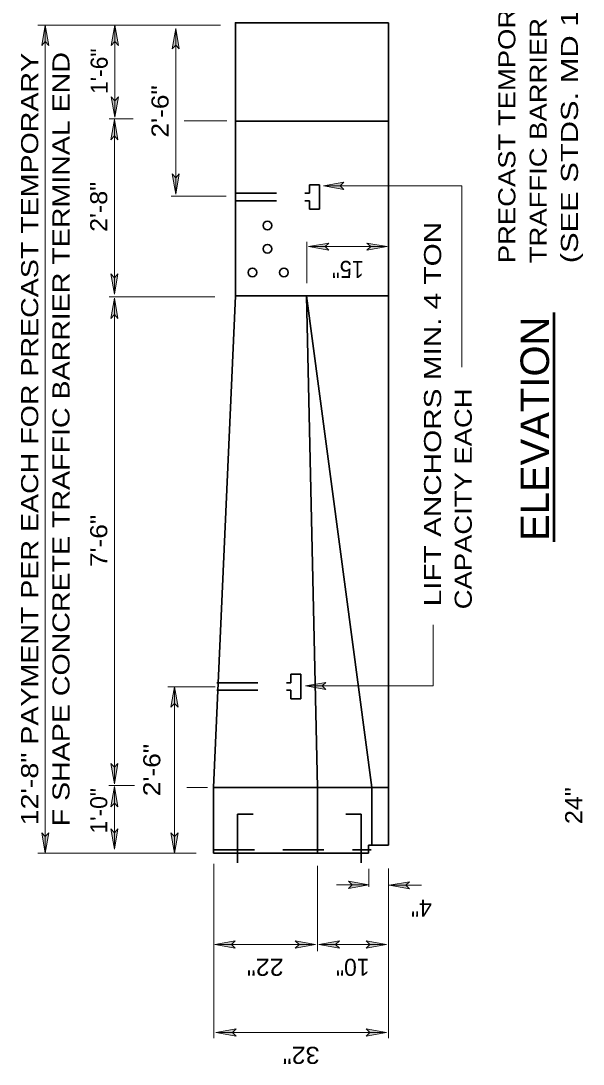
# Model space of a CAD drawing. Extents: x 12.6 to 19.4, y 6.1 to 16.3.
# Drawn here: x 15.209 to 17.184, y 8.18 to 11.844 of the extents above; entities that cross this region are included whole.
import ezdxf
from ezdxf.enums import TextEntityAlignment as Align

# ---------------------------------------------------------------- set-up
doc = ezdxf.new("R2010")
doc.units = 0
doc.header["$LTSCALE"] = 0.024
doc.linetypes.add('LONG_DASHED', pattern=[7.5, 6, -1.5])
for name, color, linetype, lineweight in [('1', 7, 'Continuous', 35), ('10', 7, 'Continuous', 13), ('12', 7, 'Continuous', 53)]:
    doc.layers.add(name, color=color, linetype=linetype, lineweight=lineweight)

msp = doc.modelspace()

# ---------------------------------------------------------------- hatches: boundary and pattern name
at = {"layer": '10'}
for points in [[(15.2821, 11.7573), (15.2947, 11.8288), (15.3073, 11.7573), (15.2947, 11.7708)], [(15.5263, 11.7574), (15.5389, 11.8289), (15.5515, 11.7574), (15.5389, 11.7709)], [(15.7401, 11.7452), (15.7527, 11.8167), (15.7653, 11.7452), (15.7527, 11.7587)], [(15.5515, 11.5766), (15.5389, 11.5051), (15.5263, 11.5766), (15.5389, 11.5631)], [(15.5247, 11.4261), (15.5373, 11.4976), (15.5499, 11.4261), (15.5373, 11.4396)], [(15.7653, 11.3065), (15.7527, 11.235), (15.7401, 11.3065), (15.7527, 11.293)], [(16.3439, 11.2517), (16.2724, 11.2643), (16.3439, 11.2769), (16.3304, 11.2643)], [(16.2912, 11.0383), (16.2197, 11.0509), (16.2912, 11.0635), (16.2777, 11.0509)], [(16.4247, 11.0635), (16.4962, 11.0509), (16.4247, 11.0383), (16.4382, 11.0509)], [(15.5499, 10.955), (15.5373, 10.8835), (15.5247, 10.955), (15.5373, 10.9415)], [(15.5248, 10.7985), (15.5374, 10.87), (15.55, 10.7985), (15.5374, 10.812)], [(15.7362, 9.4331), (15.7488, 9.5046), (15.7614, 9.4331), (15.7488, 9.4466)], [(16.2806, 9.4951), (16.2091, 9.5077), (16.2806, 9.5203), (16.2671, 9.5077)], [(15.55, 9.2359), (15.5374, 9.1644), (15.5248, 9.2359), (15.5374, 9.2224)], [(15.5248, 9.0831), (15.5374, 9.1546), (15.55, 9.0831), (15.5374, 9.0966)], [(15.3073, 8.9921), (15.2947, 8.9206), (15.2821, 8.9921), (15.2947, 8.9786)], [(15.55, 9.0056), (15.5374, 8.9341), (15.5248, 9.0056), (15.5374, 8.9921)], [(15.7614, 8.9921), (15.7488, 8.9206), (15.7362, 8.9921), (15.7488, 8.9786)], [(16.3596, 8.8218), (16.4311, 8.8092), (16.3596, 8.7966), (16.3731, 8.8092)], [(16.5743, 8.7952), (16.5028, 8.8078), (16.5743, 8.8204), (16.5608, 8.8078)], [(15.9619, 8.5873), (15.8904, 8.5999), (15.9619, 8.6125), (15.9484, 8.5999)], [(16.1728, 8.6125), (16.2443, 8.5999), (16.1728, 8.5873), (16.1863, 8.5999)], [(16.3277, 8.5873), (16.2562, 8.5999), (16.3277, 8.6125), (16.3142, 8.5999)], [(16.4219, 8.6125), (16.4934, 8.5999), (16.4219, 8.5873), (16.4354, 8.5999)], [(15.9653, 8.278), (15.8938, 8.2906), (15.9653, 8.3032), (15.9518, 8.2906)], [(16.4219, 8.3032), (16.4934, 8.2906), (16.4219, 8.278), (16.4354, 8.2906)]]:
    msp.add_hatch(color=256, dxfattribs=at).paths.add_polyline_path(points)

# ---------------------------------------------------------------- linework, layer by layer
at = {"layer": '1'}
for p, q in [((16.5, 8.9484), (16.5, 11.8374)), ((16.5, 10.8779), (15.9627, 10.8779)), ((16.4424, 9.1509), (16.2122, 10.8779)), ((16.2505, 9.1509), (16.2122, 10.8779)), ((15.8859, 9.1509), (16.5, 9.1509)), ((16.2505, 8.9206), (16.2505, 9.1509)), ((16.4424, 8.9484), (16.4424, 9.1509)), ((16.4298, 8.9206), (16.4298, 8.9484)), ((16.5, 8.9484), (16.4298, 8.9484)), ((16.4298, 8.9206), (15.8859, 8.9206)), ((15.9699, 8.9211), (15.9699, 8.887)), ((16.4049, 8.9211), (16.4049, 8.887))]:
    msp.add_line(p, q, dxfattribs=at)
at = {"layer": '1', "linetype": 'LONG_DASHED'}
for p, q in [((16.2226, 11.2681), (16.2577, 11.2681)), ((16.2577, 11.1822), (16.2577, 11.2681)), ((15.9625, 11.212), (16.2226, 11.212)), ((16.2226, 11.1822), (16.2226, 11.212)), ((16.2226, 11.1822), (16.2577, 11.1822)), ((16.1578, 9.5491), (16.1928, 9.5491)), ((16.1928, 9.4632), (16.1928, 9.5491)), ((15.8977, 9.493), (16.1578, 9.493)), ((16.1578, 9.4632), (16.1578, 9.493)), ((16.1578, 9.4632), (16.1928, 9.4632)), ((16.3501, 9.0577), (16.4049, 9.0577)), ((16.4049, 8.9211), (16.4049, 9.0577)), ((15.8856, 8.9326), (16.4395, 8.9326))]:
    msp.add_line(p, q, dxfattribs=at)
at = {"layer": '1'}
for points in [[(16.5, 11.8374), (15.9627, 11.8374), (15.9627, 11.4919), (16.5, 11.4919)], [(15.8859, 8.9206), (15.8859, 9.1509), (15.9627, 10.8779), (15.9627, 11.4919)]]:
    msp.add_lwpolyline(points, dxfattribs=at)
at = {"layer": '1', "linetype": 'LONG_DASHED'}
for points in [[(15.9625, 11.2383), (16.2226, 11.2383), (16.2226, 11.2681)], [(15.8977, 9.5193), (16.1578, 9.5193), (16.1578, 9.5491)], [(15.9699, 8.9211), (15.9699, 9.0577), (16.0247, 9.0577)]]:
    msp.add_lwpolyline(points, dxfattribs=at)
at = {"layer": '1'}
for centre in [(16.0749, 11.1247), (16.0749, 11.0434), (16.0222, 10.9603), (16.1332, 10.9603)]:
    msp.add_circle(centre, 0.0152, dxfattribs=at)
at = {"layer": '10'}
for p, q in [((15.91, 11.8288), (15.2683, 11.8288)), ((15.2947, 11.8288), (15.2821, 11.7573)), ((15.2947, 8.9206), (15.2947, 11.8288)), ((15.2947, 11.8288), (15.3073, 11.7573)), ((15.5389, 11.8289), (15.5263, 11.7574)), ((15.5389, 11.5051), (15.5389, 11.8289)), ((15.5389, 11.8289), (15.5515, 11.7574)), ((15.7527, 11.8167), (15.7401, 11.7452)), ((15.7527, 11.235), (15.7527, 11.8167)), ((15.7527, 11.8167), (15.7653, 11.7452)), ((15.5389, 11.5051), (15.5263, 11.5766)), ((15.5389, 11.5051), (15.5515, 11.5766)), ((15.5195, 11.5001), (15.6033, 11.5001)), ((15.5373, 11.4976), (15.5247, 11.4261)), ((15.5373, 10.8835), (15.5373, 11.4976)), ((15.5373, 11.4976), (15.5499, 11.4261)), ((15.933, 11.4932), (15.7822, 11.4932)), ((15.7527, 11.235), (15.7401, 11.3065)), ((15.7527, 11.235), (15.7653, 11.3065)), ((16.2724, 11.2643), (16.3439, 11.2769)), ((16.758, 11.2643), (16.2724, 11.2643)), ((16.2724, 11.2643), (16.3439, 11.2517)), ((16.758, 11.2643), (16.758, 10.6272)), ((15.9297, 11.2285), (15.7373, 11.2285)), ((16.2132, 10.9226), (16.2132, 11.068)), ((16.2197, 11.0509), (16.2912, 11.0635)), ((16.2197, 11.0509), (16.4962, 11.0509)), ((16.2197, 11.0509), (16.2912, 11.0383)), ((16.4962, 11.0509), (16.4247, 11.0635)), ((16.4962, 11.0509), (16.4247, 11.0383)), ((15.5373, 10.8835), (15.5247, 10.955)), ((15.5373, 10.8835), (15.5499, 10.955)), ((15.8904, 10.8747), (15.5195, 10.8747)), ((15.5374, 10.87), (15.5248, 10.7985)), ((15.5374, 9.1644), (15.5374, 10.87)), ((15.5374, 10.87), (15.55, 10.7985)), ((16.6576, 9.7223), (16.6576, 9.5077)), ((15.8914, 9.5046), (15.7246, 9.5046)), ((15.7488, 9.5046), (15.7362, 9.4331)), ((15.7488, 8.9206), (15.7488, 9.5046)), ((15.7488, 9.5046), (15.7614, 9.4331)), ((16.2091, 9.5077), (16.2806, 9.5203)), ((16.6576, 9.5077), (16.2091, 9.5077)), ((16.2091, 9.5077), (16.2806, 9.4951)), ((15.5374, 9.1644), (15.5248, 9.2359)), ((15.5374, 9.1644), (15.55, 9.2359)), ((15.5177, 9.1579), (15.6076, 9.1579)), ((15.5374, 9.1546), (15.5248, 9.0831)), ((15.5374, 9.1546), (15.5374, 8.9341)), ((15.5374, 9.1546), (15.55, 9.0831)), ((15.8641, 9.1509), (15.792, 9.1509)), ((15.2947, 8.9206), (15.2821, 8.9921)), ((15.2947, 8.9206), (15.3073, 8.9921)), ((15.5374, 8.9341), (15.5248, 9.0056)), ((15.5374, 8.9341), (15.55, 9.0056)), ((15.7488, 8.9206), (15.7362, 8.9921)), ((15.7488, 8.9206), (15.7614, 8.9921)), ((15.8248, 8.9206), (15.2683, 8.9206)), ((15.887, 8.8828), (15.887, 8.2709)), ((16.2508, 8.8762), (16.2508, 8.5767)), ((16.4312, 8.8653), (16.4312, 8.8026)), ((16.5, 8.8664), (16.5, 8.2709)), ((16.3178, 8.8092), (16.4311, 8.8092)), ((16.4311, 8.8092), (16.3596, 8.8218)), ((16.4311, 8.8092), (16.3596, 8.7966)), ((16.5028, 8.8078), (16.5743, 8.8204)), ((16.5028, 8.8078), (16.6161, 8.8078)), ((16.5028, 8.8078), (16.5743, 8.7952)), ((15.8904, 8.5999), (15.9619, 8.6125)), ((16.2443, 8.5999), (16.1728, 8.6125)), ((16.2562, 8.5999), (16.3277, 8.6125)), ((16.4934, 8.5999), (16.4219, 8.6125)), ((16.2443, 8.5999), (15.8904, 8.5999)), ((15.8904, 8.5999), (15.9619, 8.5873)), ((16.2443, 8.5999), (16.1728, 8.5873)), ((16.4934, 8.5999), (16.2562, 8.5999)), ((16.2562, 8.5999), (16.3277, 8.5873)), ((16.4934, 8.5999), (16.4219, 8.5873)), ((15.8938, 8.2906), (15.9653, 8.3032)), ((16.4934, 8.2906), (15.8938, 8.2906)), ((15.8938, 8.2906), (15.9653, 8.278)), ((16.4934, 8.2906), (16.4219, 8.3032)), ((16.4934, 8.2906), (16.4219, 8.278))]:
    msp.add_line(p, q, dxfattribs=at)
for points in [[(15.2821, 11.7573), (15.2947, 11.8288), (15.3073, 11.7573), (15.2947, 11.7708)], [(15.5263, 11.7574), (15.5389, 11.8289), (15.5515, 11.7574), (15.5389, 11.7709)], [(15.7401, 11.7452), (15.7527, 11.8167), (15.7653, 11.7452), (15.7527, 11.7587)], [(15.5515, 11.5766), (15.5389, 11.5051), (15.5263, 11.5766), (15.5389, 11.5631)], [(15.5247, 11.4261), (15.5373, 11.4976), (15.5499, 11.4261), (15.5373, 11.4396)], [(15.7653, 11.3065), (15.7527, 11.235), (15.7401, 11.3065), (15.7527, 11.293)], [(16.3439, 11.2517), (16.2724, 11.2643), (16.3439, 11.2769), (16.3304, 11.2643)], [(16.2912, 11.0383), (16.2197, 11.0509), (16.2912, 11.0635), (16.2777, 11.0509)], [(16.4247, 11.0635), (16.4962, 11.0509), (16.4247, 11.0383), (16.4382, 11.0509)], [(15.5499, 10.955), (15.5373, 10.8835), (15.5247, 10.955), (15.5373, 10.9415)], [(15.5248, 10.7985), (15.5374, 10.87), (15.55, 10.7985), (15.5374, 10.812)], [(15.7362, 9.4331), (15.7488, 9.5046), (15.7614, 9.4331), (15.7488, 9.4466)], [(16.2806, 9.4951), (16.2091, 9.5077), (16.2806, 9.5203), (16.2671, 9.5077)], [(15.55, 9.2359), (15.5374, 9.1644), (15.5248, 9.2359), (15.5374, 9.2224)], [(15.5248, 9.0831), (15.5374, 9.1546), (15.55, 9.0831), (15.5374, 9.0966)], [(15.3073, 8.9921), (15.2947, 8.9206), (15.2821, 8.9921), (15.2947, 8.9786)], [(15.55, 9.0056), (15.5374, 8.9341), (15.5248, 9.0056), (15.5374, 8.9921)], [(15.7614, 8.9921), (15.7488, 8.9206), (15.7362, 8.9921), (15.7488, 8.9786)], [(16.3596, 8.8218), (16.4311, 8.8092), (16.3596, 8.7966), (16.3731, 8.8092)], [(16.5743, 8.7952), (16.5028, 8.8078), (16.5743, 8.8204), (16.5608, 8.8078)], [(15.9619, 8.5873), (15.8904, 8.5999), (15.9619, 8.6125), (15.9484, 8.5999)], [(16.1728, 8.6125), (16.2443, 8.5999), (16.1728, 8.5873), (16.1863, 8.5999)], [(16.3277, 8.5873), (16.2562, 8.5999), (16.3277, 8.6125), (16.3142, 8.5999)], [(16.4219, 8.6125), (16.4934, 8.5999), (16.4219, 8.5873), (16.4354, 8.5999)], [(15.9653, 8.278), (15.8938, 8.2906), (15.9653, 8.3032), (15.9518, 8.2906)], [(16.4219, 8.3032), (16.4934, 8.2906), (16.4219, 8.278), (16.4354, 8.2906)]]:
    msp.add_lwpolyline(points, close=True, dxfattribs=at)
for points in [[(15.2821, 11.7573), (15.2947, 11.7708), (15.3073, 11.7573)], [(15.5263, 11.7574), (15.5389, 11.7709), (15.5515, 11.7574)], [(15.7401, 11.7452), (15.7527, 11.7587), (15.7653, 11.7452)], [(15.5515, 11.5766), (15.5389, 11.5631), (15.5263, 11.5766)], [(15.5247, 11.4261), (15.5373, 11.4396), (15.5499, 11.4261)], [(15.7653, 11.3065), (15.7527, 11.293), (15.7401, 11.3065)], [(16.3439, 11.2517), (16.3304, 11.2643), (16.3439, 11.2769)], [(16.2912, 11.0383), (16.2777, 11.0509), (16.2912, 11.0635)], [(16.4247, 11.0635), (16.4382, 11.0509), (16.4247, 11.0383)], [(15.5499, 10.955), (15.5373, 10.9415), (15.5247, 10.955)], [(15.5248, 10.7985), (15.5374, 10.812), (15.55, 10.7985)], [(16.2806, 9.4951), (16.2671, 9.5077), (16.2806, 9.5203)], [(15.7362, 9.4331), (15.7488, 9.4466), (15.7614, 9.4331)], [(15.55, 9.2359), (15.5374, 9.2224), (15.5248, 9.2359)], [(15.5248, 9.0831), (15.5374, 9.0966), (15.55, 9.0831)], [(15.3073, 8.9921), (15.2947, 8.9786), (15.2821, 8.9921)], [(15.55, 9.0056), (15.5374, 8.9921), (15.5248, 9.0056)], [(15.7614, 8.9921), (15.7488, 8.9786), (15.7362, 8.9921)], [(16.3596, 8.8218), (16.3731, 8.8092), (16.3596, 8.7966)], [(16.5743, 8.7952), (16.5608, 8.8078), (16.5743, 8.8204)], [(15.9619, 8.5873), (15.9484, 8.5999), (15.9619, 8.6125)], [(16.1728, 8.6125), (16.1863, 8.5999), (16.1728, 8.5873)], [(16.3277, 8.5873), (16.3142, 8.5999), (16.3277, 8.6125)], [(16.4219, 8.6125), (16.4354, 8.5999), (16.4219, 8.5873)], [(15.9653, 8.278), (15.9518, 8.2906), (15.9653, 8.3032)], [(16.4219, 8.3032), (16.4354, 8.2906), (16.4219, 8.278)]]:
    msp.add_lwpolyline(points, dxfattribs=at)
at = {"layer": '12'}
msp.add_line((17.083, 10.0144), (17.083, 10.8196), dxfattribs=at)

# ---------------------------------------------------------------- texts
for s, width, p in [('PRECAST TEMPORARY CONCRETE', 1.2, (16.9462, 10.9927)), ('(SEE STDS. MD 104.01-53 &', 1.35, (17.1662, 10.9926)), ('TRAFFIC BARRIER', 1.2, (17.0562, 10.9927)), ('LIFT ANCHORS MIN. 4 TON', 1.3, (16.6853, 9.7877)), ('CAPACITY EACH', 1.2, (16.793, 9.7771))]:
    msp.add_text(s, height=0.06, rotation=90, dxfattribs=dict(at, width=width)).set_placement(p)
for s, height, rotation, width, p in [('12\'-8" PAYMENT PER EACH FOR PRECAST TEMPORARY', 0.06, 90, 1.25, (15.2697, 10.3748)), ('F SHAPE CONCRETE TRAFFIC BARRIER TERMINAL END', 0.06, 90, 1.25, (15.3797, 10.3747)), ('2\'-6"', 0.06, 90, 1.15, (15.7277, 11.5258)), ('2\'-8"', 0.06, 90, 1.1, (15.5123, 11.1905)), ('15"', 0.06, 180, 0.95, (16.358, 11.0008)), ('ELEVATION', 0.1, 90, 1.05, (17.0642, 10.4111)), ('7\'-6"', 0.06, 90, 1.15, (15.5124, 10.0172)), ('2\'-6"', 0.06, 90, 1.15, (15.6988, 9.2126)), ('24"', 0.06, 90, 1.1, (17.181, 9.0874)), ('22"', 0.06, 180, 1.1, (16.0674, 8.5498)), ('32"', 0.06, 180, 1.1, (16.1936, 8.2405))]:
    msp.add_text(s, height=height, rotation=rotation, dxfattribs=dict(at, width=width)).set_placement(p, align=Align.CENTER)
for s, rotation, p in [('1\'-6"', 90, (15.5139, 11.6669)), ('1\'-0"', 90, (15.5124, 9.0694)), ('4"', 180, (16.6161, 8.7577)), ('10"', 180, (16.3747, 8.5498))]:
    msp.add_text(s, height=0.06, rotation=rotation, dxfattribs=at).set_placement(p, align=Align.CENTER)

doc.saveas('drawing.dxf')
